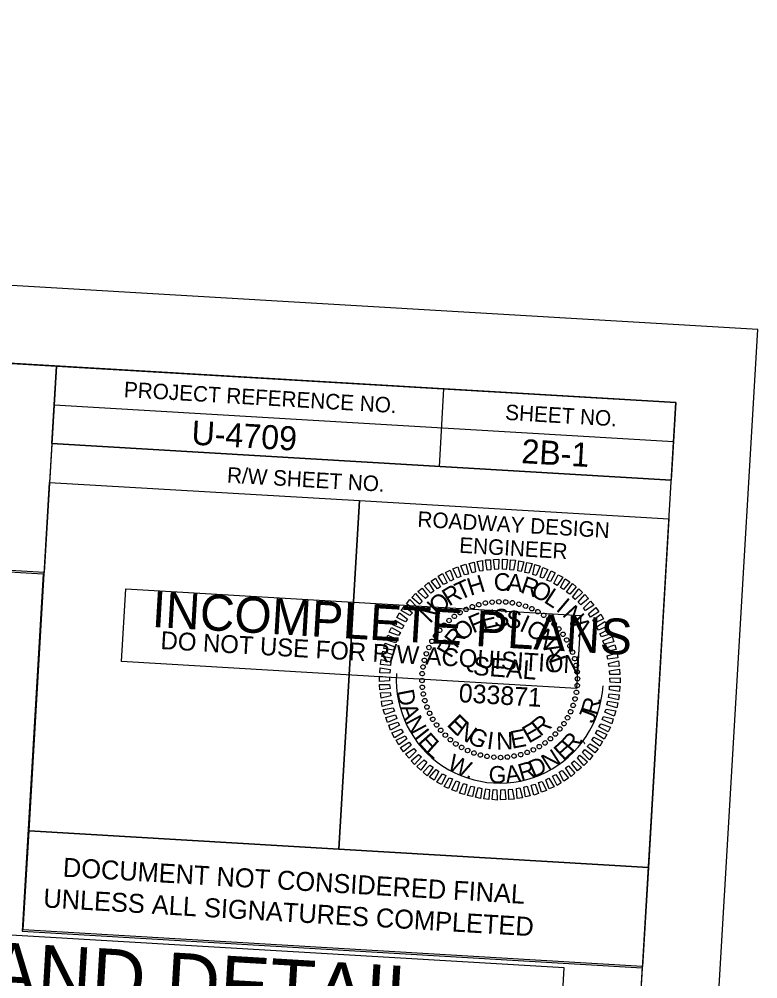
# Model space of a CAD drawing. Extents: x 2011491 to 2012372, y 444688 to 445287.
# Drawn here: x 2012252.9 to 2012371.9, y 445132.9 to 445287.5 of the extents above; entities that cross this region are included whole.
import ezdxf

# ---------------------------------------------------------------- set-up
doc = ezdxf.new("R2010")
doc.units = 0
for name, color, linetype in [('Old_Level_1', 7, 'Continuous'), ('Old_Level_58', 7, 'Continuous'), ('Prop Dimension', 7, 'Continuous'), ('Scratch_Level_0', 7, 'Continuous'), ('Sheet Clip Boundary CELL', 7, 'Continuous'), ('Sheet Data Field CELL', 7, 'Continuous'), ('Sheet Plan And Profile CELL', 7, 'Continuous'), ('Sheet Plot Border Outside CELL', 7, 'Continuous'), ('Sheet Professional Seal CELL', 7, 'Continuous'), ('Sheet Profile Grid Minor CELL', 7, 'Continuous'), ('Sheet Sticker Exception Certification CELL', 7, 'Continuous'), ('Sheet Sticker Incomplete CELL', 7, 'Continuous')]:
    doc.layers.add(name, color=color, linetype=linetype)

msp = doc.modelspace()

# ---------------------------------------------------------------- linework, layer by layer
at = {"layer": 'Old_Level_1'}
msp.add_lwpolyline([(2012193.42, 445130.88), (2012339.99, 445122.24), (2012340.72, 445134.62), (2012194.15, 445143.26)], close=True, dxfattribs=at)
at = {"layer": 'Old_Level_58'}
msp.add_lwpolyline([(2012159.02, 445237.47), (2012258.87, 445231.58), (2012256.91, 445198.29), (2012157.05, 445204.18)], close=True, dxfattribs=at)
at = {"layer": 'Scratch_Level_0'}
msp.add_arc((2012330.33, 445181.06), 16.68, 176.6264, 356.6264, dxfattribs=at)
at = {"layer": 'Sheet Clip Boundary CELL'}
for points in [[(2012353.36, 445134.84), (2012253.51, 445140.73), (2012256.91, 445198.29), (2012157.05, 445204.18), (2012159.02, 445237.47), (2011610.02, 445269.83), (2011579.13, 444745.74), (2012327.83, 444701.6)], [(2011579.79, 444746.22), (2011610.64, 445269.52), (2012158.83, 445237.2), (2012156.87, 445204), (2012256.73, 445198.11), (2012253.34, 445140.51), (2012353.28, 445134.62), (2012327.76, 444701.71)]]:
    msp.add_lwpolyline(points, close=True, dxfattribs=at)
at = {"layer": 'Sheet Plan And Profile CELL'}
for p, q in [((2012321.28, 445227.88), (2012320.55, 445215.4)), ((2012258.5, 445225.32), (2012358.35, 445219.43)), ((2012258.13, 445219.08), (2012257.76, 445212.84)), ((2012258.13, 445219.08), (2012357.98, 445213.19)), ((2012307.7, 445209.89), (2012304.39, 445153.77))]:
    msp.add_line(p, q, dxfattribs=at)
for points in [[(2012358.72, 445225.69), (2011610.02, 445269.83), (2011579.13, 444745.74), (2012327.83, 444701.6)], [(2012258.87, 445231.58), (2012358.72, 445225.69), (2012357.98, 445213.19), (2012258.13, 445219.08)], [(2012257.76, 445212.84), (2012307.7, 445209.89), (2012304.39, 445153.74), (2012254.45, 445156.68)], [(2012307.7, 445209.89), (2012357.61, 445206.95), (2012354.3, 445150.8), (2012304.39, 445153.74)]]:
    msp.add_lwpolyline(points, close=True, dxfattribs=at)
at = {"layer": 'Sheet Plot Border Outside CELL'}
msp.add_lwpolyline([(2011491.04, 444738.41), (2012339.57, 444688.39), (2012371.93, 445237.44), (2011523.41, 445287.46)], close=True, dxfattribs=at)
at = {"layer": 'Sheet Professional Seal CELL'}
for p, q in [((2012325.91, 445192.82), (2012325.91, 445192.82)), ((2012326.93, 445193.16), (2012326.93, 445193.16)), ((2012328, 445193.39), (2012328, 445193.39)), ((2012329.11, 445193.53), (2012329.11, 445193.53)), ((2012330.19, 445193.62), (2012330.19, 445193.62)), ((2012331.29, 445193.58), (2012331.29, 445193.58)), ((2012332.39, 445193.44), (2012332.39, 445193.44)), ((2012333.45, 445193.2), (2012333.45, 445193.2)), ((2012334.48, 445192.91), (2012334.48, 445192.91)), ((2012323.02, 445191.28), (2012323.02, 445191.28)), ((2012323.93, 445191.86), (2012323.93, 445191.86)), ((2012324.91, 445192.37), (2012324.91, 445192.37)), ((2012335.51, 445192.5), (2012335.51, 445192.5)), ((2012336.48, 445191.99), (2012336.48, 445191.99)), ((2012337.43, 445191.44), (2012337.43, 445191.44)), ((2012321.36, 445189.85), (2012321.36, 445189.85)), ((2012322.15, 445190.58), (2012322.15, 445190.58)), ((2012338.29, 445190.76), (2012338.29, 445190.76)), ((2012339.12, 445190.03), (2012339.12, 445190.03)), ((2012319.95, 445188.16), (2012319.95, 445188.16)), ((2012320.63, 445189.02), (2012320.63, 445189.02)), ((2012339.85, 445189.24), (2012339.85, 445189.24)), ((2012340.55, 445188.37), (2012340.55, 445188.37)), ((2012319.4, 445187.22), (2012319.4, 445187.22)), ((2012341.12, 445187.46), (2012341.12, 445187.46)), ((2012318.48, 445185.22), (2012318.48, 445185.22)), ((2012318.89, 445186.24), (2012318.89, 445186.24)), ((2012341.64, 445186.48), (2012341.64, 445186.48)), ((2012342.08, 445185.48), (2012342.08, 445185.48)), ((2012318.19, 445184.18), (2012318.19, 445184.18)), ((2012342.42, 445184.46), (2012342.42, 445184.46)), ((2012317.81, 445182.02), (2012317.81, 445182.02)), ((2012317.95, 445183.12), (2012317.95, 445183.12)), ((2012342.66, 445183.39), (2012342.66, 445183.39)), ((2012342.8, 445182.28), (2012342.8, 445182.28)), ((2012317.77, 445180.93), (2012317.77, 445180.93)), ((2012330.33, 445181.06), (2012330.33, 445181.06)), ((2012342.88, 445181.2), (2012342.88, 445181.2)), ((2012317.86, 445179.84), (2012317.86, 445179.84)), ((2012342.7, 445179), (2012342.7, 445179)), ((2012342.84, 445180.1), (2012342.84, 445180.1)), ((2012318, 445178.73), (2012318, 445178.73)), ((2012318.23, 445177.67), (2012318.23, 445177.67)), ((2012342.47, 445177.94), (2012342.47, 445177.94)), ((2012318.57, 445176.65), (2012318.57, 445176.65)), ((2012341.77, 445175.88), (2012341.77, 445175.88)), ((2012342.18, 445176.91), (2012342.18, 445176.91)), ((2012319.02, 445175.64), (2012319.02, 445175.64)), ((2012319.53, 445174.66), (2012319.53, 445174.66)), ((2012341.26, 445174.91), (2012341.26, 445174.91)), ((2012320.11, 445173.75), (2012320.11, 445173.75)), ((2012320.81, 445172.88), (2012320.81, 445172.88)), ((2012340.03, 445173.1), (2012340.03, 445173.1)), ((2012340.7, 445173.96), (2012340.7, 445173.96)), ((2012321.54, 445172.09), (2012321.54, 445172.09)), ((2012322.37, 445171.36), (2012322.37, 445171.36)), ((2012338.51, 445171.54), (2012338.51, 445171.54)), ((2012339.3, 445172.27), (2012339.3, 445172.27)), ((2012323.23, 445170.69), (2012323.23, 445170.69)), ((2012324.17, 445170.13), (2012324.17, 445170.13)), ((2012325.15, 445169.62), (2012325.15, 445169.62)), ((2012335.75, 445169.75), (2012335.75, 445169.75)), ((2012336.73, 445170.27), (2012336.73, 445170.27)), ((2012337.64, 445170.84), (2012337.64, 445170.84)), ((2012326.17, 445169.21), (2012326.17, 445169.21)), ((2012327.21, 445168.92), (2012327.21, 445168.92)), ((2012328.27, 445168.69), (2012328.27, 445168.69)), ((2012329.37, 445168.55), (2012329.37, 445168.55)), ((2012330.47, 445168.51), (2012330.47, 445168.51)), ((2012331.55, 445168.59), (2012331.55, 445168.59)), ((2012332.66, 445168.73), (2012332.66, 445168.73)), ((2012333.72, 445168.97), (2012333.72, 445168.97)), ((2012334.74, 445169.31), (2012334.74, 445169.31))]:
    msp.add_line(p, q, dxfattribs=at)
for points in [[(2012329.52, 445198.79), (2012329.34, 445200.4), (2012330.19, 445200.45), (2012330.12, 445198.83)], [(2012330.78, 445198.84), (2012330.75, 445200.47), (2012331.57, 445200.4), (2012331.37, 445198.78)], [(2012323.51, 445197.47), (2012322.79, 445198.91), (2012323.59, 445199.21), (2012324.07, 445197.66)], [(2012324.64, 445197.93), (2012324.07, 445199.41), (2012324.84, 445199.67), (2012325.27, 445198.04)], [(2012325.88, 445198.25), (2012325.4, 445199.78), (2012326.18, 445199.96), (2012326.42, 445198.4)], [(2012327.1, 445198.51), (2012326.67, 445200.11), (2012327.53, 445200.23), (2012327.63, 445198.6)], [(2012328.31, 445198.71), (2012328.01, 445200.33), (2012328.84, 445200.36), (2012328.92, 445198.75)], [(2012331.97, 445198.75), (2012332.07, 445200.37), (2012332.89, 445200.29), (2012332.57, 445198.69)], [(2012333.22, 445198.6), (2012333.41, 445200.21), (2012334.23, 445200.01), (2012333.81, 445198.46)], [(2012334.4, 445198.33), (2012334.72, 445199.91), (2012335.54, 445199.74), (2012335, 445198.22)], [(2012335.66, 445197.98), (2012336, 445199.58), (2012336.84, 445199.33), (2012336.18, 445197.82)], [(2012336.84, 445197.58), (2012337.3, 445199.11), (2012338.06, 445198.81), (2012337.35, 445197.38)], [(2012320.27, 445195.68), (2012319.27, 445196.94), (2012319.97, 445197.42), (2012320.76, 445195.98)], [(2012321.26, 445196.37), (2012320.42, 445197.7), (2012321.09, 445198.13), (2012321.83, 445196.64)], [(2012322.4, 445196.93), (2012321.56, 445198.33), (2012322.35, 445198.69), (2012322.89, 445197.2)], [(2012337.93, 445197.07), (2012338.6, 445198.61), (2012339.28, 445198.26), (2012338.5, 445196.86)], [(2012339.03, 445196.53), (2012339.74, 445197.96), (2012340.49, 445197.57), (2012339.56, 445196.22)], [(2012318.35, 445194.14), (2012317.14, 445195.24), (2012317.8, 445195.77), (2012318.78, 445194.51)], [(2012319.23, 445194.96), (2012318.19, 445196.13), (2012318.83, 445196.69), (2012319.72, 445195.29)], [(2012340.14, 445195.88), (2012340.9, 445197.27), (2012341.62, 445196.8), (2012340.6, 445195.56)], [(2012341.08, 445195.15), (2012342.04, 445196.55), (2012342.65, 445195.99), (2012341.61, 445194.82)], [(2012317.42, 445193.24), (2012316.18, 445194.29), (2012316.77, 445194.91), (2012317.8, 445193.67)], [(2012342.06, 445194.34), (2012343.06, 445195.66), (2012343.68, 445195.08), (2012342.51, 445193.97)], [(2012342.96, 445193.51), (2012344.06, 445194.75), (2012344.62, 445194.12), (2012343.41, 445193.11)], [(2012315.81, 445191.38), (2012314.46, 445192.21), (2012315, 445192.88), (2012316.24, 445191.81)], [(2012316.62, 445192.34), (2012315.32, 445193.27), (2012315.84, 445193.96), (2012316.97, 445192.79)], [(2012343.81, 445192.59), (2012344.95, 445193.7), (2012345.51, 445193.06), (2012344.16, 445192.17)], [(2012344.63, 445191.64), (2012345.84, 445192.69), (2012346.32, 445191.99), (2012344.95, 445191.12)], [(2012315.15, 445190.35), (2012313.76, 445191.05), (2012314.18, 445191.81), (2012315.48, 445190.8)], [(2012345.32, 445190.62), (2012346.6, 445191.6), (2012347.03, 445190.85), (2012345.59, 445190.13)], [(2012314.58, 445189.23), (2012313.07, 445189.89), (2012313.49, 445190.64), (2012314.86, 445189.76)], [(2012345.91, 445189.56), (2012347.28, 445190.43), (2012347.71, 445189.65), (2012346.23, 445189.04)], [(2012313.57, 445186.98), (2012312.05, 445187.4), (2012312.27, 445188.21), (2012313.8, 445187.5)], [(2012314.02, 445188.16), (2012312.5, 445188.7), (2012312.87, 445189.45), (2012314.32, 445188.67)], [(2012346.49, 445188.42), (2012347.94, 445189.21), (2012348.22, 445188.42), (2012346.76, 445187.93)], [(2012313.18, 445185.8), (2012311.64, 445186.09), (2012311.87, 445186.93), (2012313.41, 445186.32)], [(2012346.93, 445187.32), (2012348.44, 445187.98), (2012348.72, 445187.16), (2012347.14, 445186.76)], [(2012347.31, 445186.12), (2012348.87, 445186.68), (2012349.1, 445185.89), (2012347.52, 445185.58)], [(2012312.9, 445184.54), (2012311.32, 445184.79), (2012311.47, 445185.63), (2012313.06, 445185.13)], [(2012347.63, 445184.9), (2012349.27, 445185.38), (2012349.37, 445184.55), (2012347.78, 445184.37)], [(2012312.71, 445183.35), (2012311.09, 445183.5), (2012311.19, 445184.32), (2012312.79, 445183.95)], [(2012347.86, 445183.68), (2012349.46, 445184.07), (2012349.56, 445183.21), (2012347.98, 445183.15)], [(2012312.61, 445182.11), (2012310.98, 445182.13), (2012311.03, 445182.98), (2012312.64, 445182.7)], [(2012348.02, 445182.47), (2012349.66, 445182.73), (2012349.69, 445181.87), (2012348.08, 445181.87)], [(2012312.56, 445180.86), (2012310.93, 445180.75), (2012310.93, 445181.6), (2012312.55, 445181.46)], [(2012348.1, 445181.27), (2012349.73, 445181.37), (2012349.73, 445180.52), (2012348.11, 445180.66)], [(2012312.64, 445179.65), (2012311, 445179.4), (2012310.97, 445180.25), (2012312.58, 445180.25)], [(2012312.79, 445178.44), (2012311.19, 445178.06), (2012311.09, 445178.91), (2012312.68, 445178.97)], [(2012347.95, 445178.77), (2012349.57, 445178.63), (2012349.47, 445177.8), (2012347.86, 445178.17)], [(2012348.05, 445180.02), (2012349.67, 445180), (2012349.62, 445179.15), (2012348.01, 445179.42)], [(2012313.02, 445177.22), (2012311.39, 445176.74), (2012311.29, 445177.58), (2012312.88, 445177.76)], [(2012347.75, 445177.58), (2012349.34, 445177.34), (2012349.19, 445176.49), (2012347.59, 445176.99)], [(2012313.35, 445176), (2012311.79, 445175.44), (2012311.56, 445176.23), (2012313.13, 445176.54)], [(2012347.48, 445176.32), (2012349.02, 445176.03), (2012348.79, 445175.19), (2012347.25, 445175.81)], [(2012313.73, 445174.8), (2012312.22, 445174.14), (2012311.94, 445174.96), (2012313.51, 445175.37)], [(2012314.17, 445173.7), (2012312.72, 445172.91), (2012312.44, 445173.7), (2012313.9, 445174.19)], [(2012347.08, 445175.14), (2012348.61, 445174.72), (2012348.39, 445173.91), (2012346.85, 445174.63)], [(2012314.75, 445172.56), (2012313.37, 445171.69), (2012312.94, 445172.47), (2012314.43, 445173.08)], [(2012346.08, 445172.9), (2012347.59, 445172.23), (2012347.17, 445171.48), (2012345.79, 445172.36)], [(2012346.64, 445173.96), (2012348.16, 445173.42), (2012347.79, 445172.67), (2012346.33, 445173.46)], [(2012315.34, 445171.5), (2012314.06, 445170.53), (2012313.62, 445171.28), (2012315.07, 445171.99)], [(2012345.51, 445171.78), (2012346.89, 445171.07), (2012346.47, 445170.32), (2012345.18, 445171.32)], [(2012316.03, 445170.48), (2012314.82, 445169.43), (2012314.33, 445170.13), (2012315.71, 445171)], [(2012316.85, 445169.53), (2012315.71, 445168.42), (2012315.15, 445169.06), (2012316.5, 445169.96)], [(2012344.04, 445169.79), (2012345.34, 445168.86), (2012344.82, 445168.16), (2012343.69, 445169.33)], [(2012344.85, 445170.74), (2012346.2, 445169.91), (2012345.66, 445169.24), (2012344.42, 445170.31)], [(2012317.7, 445168.61), (2012316.6, 445167.37), (2012316.04, 445168), (2012317.25, 445169.01)], [(2012318.6, 445167.78), (2012317.6, 445166.46), (2012316.98, 445167.05), (2012318.15, 445168.16)], [(2012342.31, 445167.98), (2012343.52, 445166.89), (2012342.86, 445166.35), (2012341.88, 445167.61)], [(2012343.23, 445168.88), (2012344.47, 445167.83), (2012343.89, 445167.21), (2012342.86, 445168.45)], [(2012319.58, 445166.97), (2012318.62, 445165.57), (2012318, 445166.14), (2012319.05, 445167.3)], [(2012320.51, 445166.24), (2012319.76, 445164.86), (2012319.03, 445165.32), (2012320.06, 445166.57)], [(2012340.39, 445166.44), (2012341.39, 445165.18), (2012340.68, 445164.7), (2012339.89, 445166.15)], [(2012341.43, 445167.16), (2012342.46, 445166), (2012341.83, 445165.43), (2012340.94, 445166.84)], [(2012321.63, 445165.6), (2012320.92, 445164.16), (2012320.17, 445164.56), (2012321.1, 445165.9)], [(2012322.72, 445165.06), (2012322.06, 445163.52), (2012321.38, 445163.86), (2012322.16, 445165.26)], [(2012338.26, 445165.19), (2012339.1, 445163.79), (2012338.31, 445163.44), (2012337.77, 445164.92)], [(2012339.39, 445165.75), (2012340.24, 445164.42), (2012339.57, 445163.99), (2012338.83, 445165.48)], [(2012323.82, 445164.54), (2012323.35, 445163.02), (2012322.6, 445163.31), (2012323.31, 445164.75)], [(2012325, 445164.15), (2012324.65, 445162.54), (2012323.82, 445162.79), (2012324.48, 445164.3)], [(2012326.26, 445163.8), (2012325.94, 445162.21), (2012325.12, 445162.39), (2012325.66, 445163.91)], [(2012327.44, 445163.53), (2012327.25, 445161.91), (2012326.43, 445162.11), (2012326.85, 445163.66)], [(2012328.69, 445163.38), (2012328.59, 445161.76), (2012327.77, 445161.83), (2012328.09, 445163.44)], [(2012329.88, 445163.28), (2012329.91, 445161.65), (2012329.09, 445161.73), (2012329.28, 445163.34)], [(2012331.14, 445163.33), (2012331.32, 445161.72), (2012330.46, 445161.67), (2012330.53, 445163.29)], [(2012332.34, 445163.41), (2012332.65, 445161.79), (2012331.82, 445161.77), (2012331.74, 445163.37)], [(2012333.56, 445163.62), (2012333.99, 445162.01), (2012333.13, 445161.89), (2012333.03, 445163.52)], [(2012334.77, 445163.87), (2012335.26, 445162.34), (2012334.47, 445162.16), (2012334.24, 445163.73)], [(2012336.02, 445164.2), (2012336.58, 445162.71), (2012335.82, 445162.46), (2012335.39, 445164.08)], [(2012337.15, 445164.66), (2012337.87, 445163.21), (2012337.07, 445162.91), (2012336.59, 445164.46)]]:
    msp.add_lwpolyline(points, close=True, dxfattribs=at)
for centre, major_axis in [((2012324.91, 445192.37), (-0.156, 0.325)), ((2012325.91, 445192.8), (-0.127, 0.337)), ((2012326.95, 445193.14), (-0.097, 0.347)), ((2012328.02, 445193.39), (-0.066, 0.354)), ((2012329.1, 445193.54), (-0.035, 0.358)), ((2012330.19, 445193.6), (-0.004, 0.36)), ((2012331.29, 445193.56), (0.027, 0.359)), ((2012332.37, 445193.43), (0.059, 0.355)), ((2012333.44, 445193.21), (0.089, 0.349)), ((2012334.49, 445192.89), (0.119, 0.34)), ((2012335.5, 445192.48), (0.149, 0.328)), ((2012323.02, 445191.25), (-0.21, 0.293)), ((2012323.94, 445191.85), (-0.183, 0.31)), ((2012336.48, 445191.99), (0.177, 0.314)), ((2012337.41, 445191.41), (0.203, 0.297)), ((2012338.28, 445190.76), (0.228, 0.278)), ((2012321.37, 445189.83), (-0.257, 0.252)), ((2012322.16, 445190.58), (-0.234, 0.273)), ((2012339.1, 445190.02), (0.252, 0.257)), ((2012339.85, 445189.23), (0.273, 0.234)), ((2012319.98, 445188.14), (-0.297, 0.203)), ((2012320.64, 445189.02), (-0.278, 0.228)), ((2012340.52, 445188.37), (0.293, 0.21)), ((2012318.91, 445186.24), (-0.328, 0.149)), ((2012319.4, 445187.21), (-0.314, 0.177)), ((2012341.12, 445187.45), (0.31, 0.183)), ((2012341.64, 445186.49), (0.325, 0.156)), ((2012318.5, 445185.22), (-0.34, 0.119)), ((2012342.07, 445185.48), (0.337, 0.127)), ((2012317.96, 445183.1), (-0.355, 0.059)), ((2012318.18, 445184.17), (-0.349, 0.089)), ((2012342.41, 445184.44), (0.347, 0.097)), ((2012342.65, 445183.37), (0.354, 0.066)), ((2012317.83, 445182.02), (-0.359, 0.027)), ((2012342.81, 445182.29), (0.358, 0.035)), ((2012317.79, 445180.92), (-0.36, -0.004)), ((2012342.83, 445180.11), (0.359, -0.027)), ((2012342.87, 445181.2), (0.36, 0.004)), ((2012317.85, 445179.83), (-0.358, -0.035)), ((2012318, 445178.75), (-0.354, -0.066)), ((2012342.7, 445179.02), (0.355, -0.059)), ((2012318.25, 445177.68), (-0.347, -0.097)), ((2012342.16, 445176.9), (0.34, -0.119)), ((2012342.48, 445177.95), (0.349, -0.089)), ((2012318.59, 445176.64), (-0.337, -0.127)), ((2012319.02, 445175.64), (-0.325, -0.156)), ((2012341.75, 445175.89), (0.328, -0.149)), ((2012319.54, 445174.67), (-0.31, -0.183)), ((2012320.14, 445173.76), (-0.293, -0.21)), ((2012340.68, 445173.98), (0.297, -0.203)), ((2012341.26, 445174.91), (0.314, -0.177)), ((2012320.81, 445172.9), (-0.273, -0.234)), ((2012339.29, 445172.29), (0.257, -0.252)), ((2012340.02, 445173.11), (0.278, -0.228)), ((2012321.56, 445172.1), (-0.252, -0.257)), ((2012322.37, 445171.37), (-0.228, -0.278)), ((2012323.25, 445170.71), (-0.203, -0.297)), ((2012337.63, 445170.87), (0.21, -0.293)), ((2012338.49, 445171.54), (0.234, -0.273)), ((2012324.18, 445170.13), (-0.177, -0.314)), ((2012325.15, 445169.64), (-0.149, -0.328)), ((2012326.17, 445169.23), (-0.119, -0.34)), ((2012334.75, 445169.33), (0.127, -0.337)), ((2012335.75, 445169.75), (0.156, -0.325)), ((2012336.72, 445170.27), (0.183, -0.31)), ((2012327.22, 445168.91), (-0.089, -0.349)), ((2012328.29, 445168.69), (-0.059, -0.355)), ((2012329.37, 445168.56), (-0.027, -0.359)), ((2012330.47, 445168.52), (0.004, -0.36)), ((2012331.56, 445168.58), (0.035, -0.358)), ((2012332.64, 445168.74), (0.066, -0.354)), ((2012333.71, 445168.98), (0.097, -0.347))]:
    msp.add_ellipse(centre, major_axis=major_axis, ratio=0.999708, dxfattribs=at)
at = {"layer": 'Sheet Sticker Exception Certification CELL'}
for p, q in [((2012253.51, 445140.73), (2012254.45, 445156.69)), ((2012254.45, 445156.69), (2012354.31, 445150.81)), ((2012354.3, 445150.8), (2012353.36, 445134.84)), ((2012353.36, 445134.84), (2012253.51, 445140.73))]:
    msp.add_line(p, q, dxfattribs=at)
at = {"layer": 'Sheet Sticker Incomplete CELL'}
msp.add_lwpolyline([(2012269.36, 445183.98), (2012270.05, 445195.71), (2012343.42, 445191.38), (2012342.73, 445179.65)], close=True, dxfattribs=at)

# ---------------------------------------------------------------- texts
at = {"layer": 'Prop Dimension'}
msp.add_text('-L- ISLAND DETAIL', height=9, rotation=356.6264, dxfattribs=at).set_placement((2012211.53, 445131.99))
at = {"layer": 'Sheet Data Field CELL'}
for s, p in [('U-4709', (2012280.56, 445218.93)), ('2B-1', (2012333.74, 445215.95))]:
    msp.add_text(s, height=3.875, rotation=356.6264, dxfattribs=at).set_placement(p)
at = {"layer": 'Sheet Plan And Profile CELL'}
for s, p in [('PROJECT REFERENCE NO.', (2012269.69, 445226.58)), ('SHEET NO.', (2012331.16, 445222.91)), ('R/W SHEET NO.', (2012286.31, 445212.81)), ('ROADWAY DESIGN', (2012317.01, 445205.69)), ('ENGINEER', (2012323.75, 445201.51))]:
    msp.add_text(s, height=2.5, rotation=356.6264, dxfattribs=at).set_placement(p)
at = {"layer": 'Sheet Professional Seal CELL'}
for s, height, rotation, p in [('H', 2.82, 17.2459, (2012325.59, 445194.54)), ('C', 2.82, 2.8463, (2012329.44, 445195.31)), ('A', 2.82, 355.6467, (2012331.42, 445195.35)), ('R', 2.82, 341.2475, (2012333.51, 445195.12)), ('R', 2.82, 31.6469, (2012322.16, 445192.81)), ('T', 2.82, 24.4462, (2012323.92, 445193.81)), ('O', 2.82, 334.0476, (2012335.16, 445194.65)), ('L', 2.82, 326.8473, (2012337.3, 445193.6)), ('O', 2.82, 38.8482, (2012320.34, 445191.37)), ('N', 2.82, 46.0499, (2012319.11, 445189.99)), ('I', 2.82, 319.6466, (2012339.25, 445192.28)), ('N', 2.82, 312.4453, (2012340.28, 445191.44)), ('F', 2.82, 22.5935, (2012326.03, 445188.48)), ('E', 2.82, 13.2375, (2012327.67, 445189.13)), ('S', 2.82, 3.882, (2012329.43, 445189.55)), ('S', 2.82, 354.5268, (2012331.23, 445189.47)), ('I', 2.82, 335.816, (2012333.35, 445189)), ('O', 2.82, 41.3077, (2012324.3, 445187.1)), ('O', 2.82, 326.4599, (2012334.33, 445188.59)), ('A', 2.82, 305.2436, (2012341.67, 445189.88)), ('R', 2.82, 50.6661, (2012323.35, 445185.93)), ('N', 2.82, 317.103, (2012335.94, 445187.49)), ('P', 2.82, 60.0253, (2012322.46, 445184.38)), ('A', 2.82, 298.3867, (2012337.29, 445186.11)), ('L', 2.82, 289.0273, (2012338.16, 445184.33)), ('SEAL', 2.999, 355.6264, (2012325.94, 445181.82)), ('E', 2.82, 314.9033, (2012321.68, 445173.73)), ('N', 2.82, 324.2604, (2012323.1, 445172.3)), ('E', 2.82, 29.7505, (2012335, 445170.72)), ('R', 2.82, 39.1078, (2012336.84, 445171.79)), ('G', 2.82, 333.6167, (2012324.93, 445171.06)), ('I', 2.82, 352.3276, (2012328.14, 445169.92)), ('N', 2.82, 1.6828, (2012329.81, 445169.75)), ('E', 2.82, 11.0382, (2012332.3, 445169.9))]:
    msp.add_text(s, height=height, rotation=rotation, dxfattribs=at).set_placement(p)
at = {"layer": 'Sheet Profile Grid Minor CELL'}
for s, height, rotation, p in [('033871', 2.999, 356.6264, (2012323.66, 445177.44)), ('D', 2.75, 280.8946, (2012313.7, 445179.22)), ('R', 2.75, 73.9805, (2012346, 445175.18)), ('.', 2.75, 80.9069, (2012346.59, 445177.11)), ('A', 2.75, 290.0393, (2012314.2, 445176.6)), ('J', 2.75, 69.1119, (2012345.44, 445173.87)), ('N', 2.75, 298.2251, (2012315, 445174.34)), ('I', 2.75, 308.1568, (2012316.39, 445171.8)), ('E', 2.75, 311.6772, (2012316.98, 445170.96)), ('L', 2.75, 318.2602, (2012318.23, 445169.5)), ('E', 2.75, 42.4222, (2012340.6, 445167.85)), ('R', 2.75, 49.0052, (2012342.05, 445169.11)), (',', 2.75, 55.9317, (2012343.4, 445170.61)), ('N', 2.75, 32.4905, (2012338.17, 445166.28)), ('W', 2.75, 333.5156, (2012321.7, 445166.72)), ('D', 2.75, 23.3459, (2012335.72, 445165.22)), ('G', 2.75, 358.3019, (2012328.5, 445164.43)), ('A', 2.75, 8.2337, (2012331.4, 445164.36)), ('R', 2.75, 16.4194, (2012333.77, 445164.68)), ('.', 2.75, 345.1217, (2012324.76, 445165.28))]:
    msp.add_text(s, height=height, rotation=rotation, dxfattribs=at).set_placement(p)
at = {"layer": 'Sheet Sticker Exception Certification CELL'}
for s, p in [('DOCUMENT NOT CONSIDERED FINAL', (2012259.84, 445149.32)), ('UNLESS ALL SIGNATURES COMPLETED', (2012256.68, 445144.37))]:
    msp.add_text(s, height=3.062, rotation=356.6264, dxfattribs=at).set_placement(p)
at = {"layer": 'Sheet Sticker Incomplete CELL'}
for s, height, p in [('INCOMPLETE PLANS', 5.76, (2012274.17, 445189.56)), ('DO NOT USE FOR R/W ACQUISITION', 2.88, (2012275.59, 445185.99))]:
    msp.add_text(s, height=height, rotation=356.6264, dxfattribs=at).set_placement(p)

doc.saveas('drawing.dxf')
